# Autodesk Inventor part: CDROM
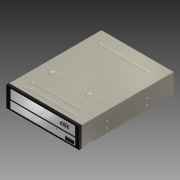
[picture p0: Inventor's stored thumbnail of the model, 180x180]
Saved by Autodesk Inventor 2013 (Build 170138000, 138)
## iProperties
Company: Autodesk Inc.
Created: 2005-12
Part Number: CDROM
Document SubType Name: Modeling
Designer: Autodesk Inc.
Density: 1 g/cm^3
Mass: 1074.93 g
Surface Area: 916.609 cm^2
Volume: 1074.93 cm^3
Material: Allgemein
Title: Personal Computer
Author: Autodesk Inc.
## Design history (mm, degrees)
sketch "Sketch5"
  geometry: L1 (0, 0)-(40, 0); L2 (40, 0)-(40, 145); L3 (40, 145)-(0, 145); L4 (0, 145)-(0, 0)
  constraints: 8 end point, 2 parallel, 1 horizontal, 1 perpendicular
  dimensions: "d189" = 145 distance of L3.end L1.start; "d190" = 40 distance of L1.start L1.end
extrude "Extrusion1" new body sketch "Sketch5" distance "d1" = 190; taper "d2" = 0 deg
sketch "Sketch6"
  geometry: L1 (-190, 72.5)-(0, 72.5); L2 (-168, 122.5)-(-162, 122.5); L3 (-162, 122.5)-(-162, 22.5); L4 (-162, 22.5)-(-168, 22.5); L5 (-168, 22.5)-(-168, 122.5); L6 (-18, 122.5)-(-12, 122.5); L7 (-12, 122.5)-(-12, 22.5); L8 (-12, 22.5)-(-18, 22.5); L9 (-18, 22.5)-(-18, 122.5); L10 (-33, 122.5)-(-27, 122.5); L11 (-27, 122.5)-(-27, 22.5); L12 (-27, 22.5)-(-33, 22.5); L13 (-33, 22.5)-(-33, 122.5); L14 (-72, 120)-(-60, 120); L15 (-60, 120)-(-60, 100); L16 (-60, 100)-(-72, 100); L17 (-72, 100)-(-72, 120); L18 (-72, 45)-(-72, 25); L19 (-60, 45)-(-72, 45); L20 (-72, 25)-(-60, 25); L21 (-60, 25)-(-60, 45); L22 (-190, 145)-(-190, 0) reference; L23 (0, 0)-(-190, 0) reference; L24 (0, 145)-(0, 0) reference; L25 (0, 145)-(-190, 145) reference; 10 further points
  constraints: 42 end point, 10 horizontal alignment, 10 parallel, 8 midpoint, 8 symmetric about line, 6 horizontal, 4 perpendicular, 21 other
  dimensions: "d4" = 6 distance between parallel lines of L5 L3; "d5" = 100 distance of L2.end L3.end; "d10" = 9 distance between parallel lines of L9 L11; "d12" = 12 distance of L14.start L14.end; "d13" = 20 distance of L16.end L14.start
extrude "Extrusion2" cut sketch "Sketch6" distance "d6" = 2; taper "d7" = 0 deg
feature "FaceDraft6" dims angle "d217" = 50 deg
sketch "Sketch8"
  geometry: L1 (-35, 142)-(-19, 142); L2 (-19, 142)-(-19, 3); L3 (-19, 3)-(-35, 3); L4 (-35, 3)-(-35, 142); L5 (-40, 0)-(-40, 145); L6 (0, 0)-(-40, 0); L7 (-40, 0)-(-40, 145) reference; L8 (0, 0)-(-40, 0) reference; L9 (0, 145)-(0, 0) reference; L10 (-40, 145)-(0, 145) reference
  constraints: 12 end point, 2 parallel, 1 horizontal, 1 perpendicular
  dimensions: "d20" = 16 distance of L1.start L1.end; "d191" = 139 distance of L1.end L2.end; "d192" = 5 distance between parallel lines of L5 L4; "d193" = 3 distance between parallel lines of L6 L3
extrude "Extrusion3" cut sketch "Sketch8" distance "d21" = 12; taper "d22" = 0 deg
workplane "Work Plane1"
sketch "Sketch9"
  geometry: L1 (-35, 8.726)-(-27.5, 8.726); L2 (-27.5, 8.726)-(-27.5, 31.566); L3 (-27.5, 31.566)-(-35, 31.566); L4 (-35, 31.566)-(-35, 8.726); L5 (-34.5, 31.066)-(-29.63, 31.066); L6 (-28, 29.436)-(-28, 11.356); L7 (-29.63, 9.726)-(-34.5, 9.726); L8 (-34.5, 9.726)-(-34.5, 31.066); L9 (-35, 31.566)-(-27.5, 31.566); L10 (-27.5, 31.566)-(-27.5, 88.946); L11 (-27.5, 88.946)-(-35, 88.946); L12 (-35, 88.946)-(-35, 31.566); L13 (-34.4, 87.946)-(-28, 87.946); L14 (-28, 87.946)-(-28, 32.066); L15 (-28, 32.066)-(-34.4, 32.066); L16 (-34.4, 32.066)-(-34.4, 87.946); L17 (-35, 108.946)-(-27.5, 108.946); L18 (-27.5, 108.946)-(-27.5, 107.946); L19 (-27.5, 107.946)-(-35, 107.946); L20 (-35, 107.946)-(-35, 108.946); L21 (-35, 127.946)-(-27.5, 127.946); L22 (-27.5, 127.946)-(-27.5, 126.946); L23 (-27.5, 126.946)-(-35, 126.946); L24 (-35, 126.946)-(-35, 127.946); L25 (-30, 108.946)-(-30, 111.946); L26 (-30, 111.946)-(-29, 111.946); L27 (-29, 111.946)-(-29, 117.946); L28 (-29, 117.946)-(-30, 117.946); L29 (-30, 117.946)-(-30, 120.946); L30 (-35, 126.946)-(-34, 126.946); L31 (-34, 126.946)-(-34, 108.946); L32 (-34, 108.946)-(-35, 108.946); L33 (-35, 108.946)-(-35, 126.946); L34 (-34, 120.946)-(-29.5, 120.946); L35 (-29.5, 120.946)-(-29.5, 121.946); L36 (-29.5, 121.946)-(-34, 121.946); L37 (-34, 121.946)-(-34, 120.946); L38 (-29.5, 120.946)-(-29.5, 118.446); L39 (-29.5, 118.446)-(-28.5, 118.446); L40 (-28.5, 118.446)-(-28.5, 111.446); L41 (-28.5, 111.446)-(-29.5, 111.446); L42 (-29.5, 111.446)-(-29.5, 108.946); L43 (-29.5, 120.946)-(-30, 120.946); L44 (-30, 121.946)-(-28.5, 121.946); L45 (-28.5, 121.946)-(-28.5, 122.446); L46 (-28.5, 122.446)-(-30, 122.446); L47 (-30, 122.446)-(-30, 121.946); L48 (-28.5, 122.446)-(-29, 122.446); L49 (-29, 122.446)-(-29, 126.446); L50 (-29, 126.446)-(-28.5, 126.446); L51 (-28.5, 126.446)-(-28.5, 122.446); L52 (-28.5, 126.446)-(-30, 126.446); L53 (-30, 126.446)-(-30, 126.946); L54 (-30, 126.946)-(-28.5, 126.946); L55 (-28.5, 126.946)-(-28.5, 126.446); L56 (-29.5, 120.946)-(-30, 120.946); L57 (-29.5, 108.946)-(-30, 108.946); L58 (-35, 142)-(-19, 142) reference; L59 (-35, 3)-(-35, 142) reference; L60 (-28, 29.436)-(-29.63, 31.066); L61 (-28, 11.356)-(-29.63, 9.726)
  constraints: 118 end point, 27 parallel, 15 collinear, 14 perpendicular, 11 horizontal, 6 equal length, 5 point on line, 2 vertical alignment, 4 other
  dimensions: "d25" = 1 distance between parallel lines of L1 L7; "d26" = 0.5 distance between parallel lines of L2 L6; "d28" = 0.5 distance between parallel lines of L5 L3; "d29" = 21.34 distance between parallel lines of L7 L5; "d31" = 1 distance between parallel lines of L5 L15; "d32" = 55.88 distance between parallel lines of L15 L13; "d33" = 1 distance between parallel lines of L13 L11; "d34" = 1 distance of L17.end L18.end; "d35" = 19 distance between parallel lines of L19 L11; "d36" = 18 distance between parallel lines of L17 L23; "d37" = 3 distance of L25.start L25.end; "d38" = 1 distance of L25.end L26.end; "d39" = 4 distance between parallel lines of L31 L25; "d40" = 6 distance of L26.end L27.end; "d41" = 0.5 distance between parallel lines of L27 L40; "d42" = 0.5 distance between parallel lines of L23 L52; "d195" = 6.4 distance of L14.end L15.end; "d196" = 0.5 distance between parallel lines of L4 L8 (derived); "d197" = 2.305 distance of L6.start L5.end; "d198" = 135 deg angle of L60 L6; "d199" = 2.305 distance of L6.end L7.start; "d200" = 135 deg angle of L7 L61
extrude "Extrusion4" join sketch "Sketch9" stored distance "d43" = 10; taper "d44" = 0 deg
sketch "Sketch11"
  geometry: L1 (-28, 87.946)-(-28, 32.066) reference; L2 (-28, 32.066)-(-34.4, 32.066) reference; L3 (-28, 62.566)-(-27.5, 62.566); L4 (-27.5, 62.566)-(-27.5, 57.066); L5 (-27.5, 57.066)-(-28, 57.066); L6 (-28, 57.066)-(-28, 62.566)
  constraints: 8 end point, 2 parallel, 1 horizontal, 1 perpendicular, 1 point on line
  dimensions: "d49" = 25 distance between parallel lines of L2 L5; "d50" = 5.5 distance between parallel lines of L5 L3
extrude "Extrusion6" cut sketch "Sketch11" stored distance "d51" = 2; taper "d52" = 0 deg
sketch "Sketch13"
  geometry: L1 (-31.25, 31.03)-(-31.25, 9.03); L2 (-34.5, 9.726)-(-34.5, 31.066); L3 (-34.5, 31.066)-(-29.63, 31.066); L4 (-28, 29.436)-(-28, 11.356); L5 (-28, 20.396)-(-34.5, 20.396); C1 r 1.25 at (-31.25, 22.53); C2 r 1.25 at (-31.25, 26.798); C3 r 1.25 at (-31.25, 18.262); C4 r 1.25 at (-31.25, 13.994)
  constraints: 10 end point, 4 centre point, 4 point on line, 3 equal radius, 2 midpoint, 1 perpendicular
  dimensions: "d60" = 4.268 distance of C3.centre C1.centre; "d61" = 4.268 distance of C1.centre C2.centre (= d60); "d62" = 2.5 diameter of C2; "d204" = 4.268 distance of C4.centre C3.centre (derived); "d205" = 2.134 distance from line of L5 C1.centre (derived)
extrude "Extrusion8" join sketch "Sketch13" distance "d63" = 3; taper "d64" = 0 deg
sketch "Sketch14"
  geometry: C1 r 0.9 at (0, 0); C2 r 0.9 at (0, -4.268); C3 r 0.9 at (0, -8.536); C4 r 0.9 at (0, -12.804); C5 r 1.25 at (0, -4.268) reference; C6 r 1.25 at (0, -12.804) reference; C7 r 1.25 at (0, -8.536) reference
  constraints: 4 centre point, 3 equal radius
  dimensions: "d65" = 1.8 diameter of C1
extrude "Extrusion9" join sketch "Sketch14" distance "d66" = 5; taper "d67" = 0 deg
sketch "Sketch15"
  geometry: L1 (-34.5, 88)-(-34.5, 31); L2 (-25.5, 88)-(-34.5, 88); L3 (-27.5, 107.946)-(-35, 107.946) reference; L4 (-35, 107.946)-(-35, 88.946) reference; L5 (-35, 88.946)-(-27.5, 88.946) reference; L6 (-27.5, 88.946)-(-27.5, 62.566) reference; L7 (-27.5, 62.566)-(-28, 62.566) reference; L8 (-28, 62.566)-(-28, 87.946) reference; L9 (-28, 87.946)-(-34.4, 87.946) reference; L10 (-34.4, 87.946)-(-34.4, 32.066) reference; L11 (-34.4, 32.066)-(-28, 32.066) reference; L12 (-28, 32.066)-(-28, 57.066) reference; L13 (-28, 57.066)-(-27.5, 57.066) reference; L14 (-27.5, 57.066)-(-27.5, 8.726) reference; L15 (-27.5, 8.726)-(-35, 8.726) reference; L16 (-35, 8.726)-(-35, 3) reference; L17 (-35, 3)-(-19, 3) reference; L18 (-19, 3)-(-19, 142) reference; L19 (-19, 142)-(-35, 142) reference; L20 (-35, 142)-(-35, 127.946) reference; L21 (-35, 127.946)-(-27.5, 127.946) reference; L22 (-27.5, 127.946)-(-27.5, 126.946) reference; L23 (-27.5, 126.946)-(-28.5, 126.946) reference; L24 (-28.5, 126.946)-(-28.5, 121.946) reference; L25 (-28.5, 121.946)-(-29.5, 121.946) reference; L26 (-29.5, 121.946)-(-29.5, 118.446) reference; L27 (-29.5, 118.446)-(-28.5, 118.446) reference; L28 (-28.5, 118.446)-(-28.5, 111.446) reference; L29 (-28.5, 111.446)-(-29.5, 111.446) reference; L30 (-29.5, 111.446)-(-29.5, 108.946) reference; L31 (-29.5, 108.946)-(-27.5, 108.946) reference; L32 (-27.5, 108.946)-(-27.5, 107.946) reference; C1 r 0.5 at (-32.5, 84)
  constraints: 4 end point, 1 centre point
  dimensions: "d69" = 4 distance from line of C1.centre L2; "d70" = 1 diameter of C1; "d71" = 2 distance from line of L1 C1.centre
extrude "Extrusion10" join sketch "Sketch15" distance "d72" = 10; taper "d73" = 0 deg
workplane "Work Plane3"
sketch "Sketch16"
  geometry: L1 (-30, 111.946)-(-30, 108.946) reference; L2 (-30, 126.946)-(-30, 126.446) reference; L3 (-30, 126.946)-(-27, 126.946); L4 (-27, 126.946)-(-27, 108.946); L5 (-27, 108.946)-(-30, 108.946); L6 (-30, 108.946)-(-30, 126.946)
  constraints: 8 end point, 2 parallel, 1 horizontal, 1 perpendicular
  dimensions: "d81" = 3 distance between parallel lines of L6 L4
extrude "Extrusion11" cut sketch "Sketch16" stored distance "d82" = 10; taper "d83" = 0 deg
sketch "Sketch17"
  geometry: L1 (-34, 120.946)-(-30, 120.946) reference; L2 (-30, 127)-(-29.8, 127); L3 (-29.8, 127)-(-29.8, 126.246); L4 (-29.8, 126.246)-(-30, 126.246); L5 (-30, 126.246)-(-30, 127); L6 (-30, 121.946)-(-34, 121.946) reference; L7 (-30, 121.946)-(-29.8, 121.946); L8 (-29.8, 121.946)-(-29.8, 122.7); L9 (-29.8, 122.7)-(-30, 122.7); L10 (-30, 122.7)-(-30, 121.946); L11 (-30, 117.946)-(-29, 117.946) reference; L12 (-29, 111.946)-(-30, 111.946) reference; L13 (-30, 120.946)-(-29.8, 120.946); L14 (-29.8, 120.946)-(-29.8, 116.946); L15 (-29.8, 116.946)-(-30, 116.946); L16 (-30, 116.946)-(-30, 120.946); L17 (-30, 109)-(-29.8, 109); L18 (-29.8, 109)-(-29.8, 112.946); L19 (-29.8, 112.946)-(-30, 112.946); L20 (-30, 112.946)-(-30, 109); L21 (-30, 126.446)-(-29, 126.446) reference
  constraints: 32 end point, 8 parallel, 4 horizontal, 4 perpendicular, 3 collinear
  dimensions: "d84" = 1 distance between parallel lines of L15 L11; "d85" = 1 distance between parallel lines of L19 L12 (= d84); "d87" = 0.2 distance between parallel lines of L4 L21 (= d86); "d88" = 0.2 distance between parallel lines of L5 L3
extrude "Extrusion12" join sketch "Sketch17" stored distance "d89" = 10; taper "d90" = 0 deg
sketch "Sketch18"
  geometry: L1 (-35, 108)-(-35, 89); L2 (-30, 127.04)-(-34, 127.04); L3 (-34, 122)-(-30, 122); L4 (-30, 121.108)-(-34, 121); L5 (-32, 127.04)-(-32, 122); L6 (-32, 121.054)-(-32, 108.946); L7 (-32, 124.52)-(-30.923, 124.52); L8 (-32, 115)-(-31.161, 115); L9 (-35, 107.946)-(-35, 88.946) reference; L10 (-29.8, 126.246)-(-30, 126.246) reference; L11 (-30.73, 98.446)-(-33.27, 98.446); L12 (-30, 108.946)-(-34, 108.946) reference; C1 r 0.25 at (-32, 125.79); C2 r 0.25 at (-32, 123.25); C3 r 0.25 at (-32, 118.81); C4 r 0.25 at (-32, 116.27); C5 r 0.25 at (-32, 113.73); C6 r 0.25 at (-32, 111.19); C7 r 0.25 at (-30.73, 102.446); C8 r 0.25 at (-30.73, 98.446); C9 r 0.25 at (-30.73, 94.446); C10 r 0.25 at (-33.27, 102.446); C11 r 0.25 at (-33.27, 98.446); C12 r 0.25 at (-33.27, 94.446); 2 further points
  constraints: 18 end point, 12 centre point, 11 equal radius, 8 midpoint, 6 point on line, 5 vertical alignment, 4 horizontal alignment, 3 symmetric about line, 2 parallel, 1 perpendicular
  dimensions: "d91" = 2.54 distance of C2.centre C1.centre; "d92" = 2.54 distance of C5.centre C4.centre; "d93" = 2.54 distance of C4.centre C3.centre (= d92); "d94" = 0.5 diameter of C1; "d95" = 2.54 distance of C10.centre C7.centre; "d96" = 4 distance of L11.start C7.centre; "d97" = 4 distance of C9.centre L11.start (= d96)
extrude "Extrusion13" join sketch "Sketch18" distance "d101" = 8; taper "d102" = 0 deg
sketch "Sketch19"
  geometry: L1 (-25, 56)-(-25, 7); L2 (-19, 3)-(-19, 142); L3 (-19, 31)-(-24.8, 31); L4 (-24.8, 31)-(-24.8, 30.2); L5 (-24.8, 30.2)-(-19, 30.2); L6 (-19, 30.2)-(-19, 31); L7 (-19, 89)-(-24.8, 89); L8 (-24.8, 89)-(-24.8, 88.2); L9 (-24.8, 88.2)-(-19, 88.2); L10 (-19, 88.2)-(-19, 89); L11 (-19, 128)-(-24.8, 128); L12 (-24.8, 128)-(-24.8, 127.2); L13 (-24.8, 127.2)-(-19, 127.2); L14 (-19, 127.2)-(-19, 128)
  constraints: 28 end point, 6 parallel, 4 collinear, 3 horizontal, 3 perpendicular, 3 point on line
  dimensions: "d103" = 0.2 distance between parallel lines of L1 L4; "d104" = 0.8 distance between parallel lines of L5 L3
extrude "Extrusion14" join sketch "Sketch19" distance "d105" = 11; taper "d106" = 0 deg
sketch "Sketch20"
  geometry: L1 (166, 145)-(181, 145); L2 (181, 145)-(181, 139); L3 (181, 139)-(166, 139); L4 (166, 139)-(166, 145); L5 (15, 145)-(30, 145); L6 (30, 145)-(30, 139); L7 (30, 139)-(15, 139); L8 (15, 139)-(15, 145); L9 (15, 0)-(30, 0); L10 (30, 0)-(30, 6); L11 (30, 6)-(15, 6); L12 (15, 6)-(15, 0); L13 (166, 0)-(181, 0); L14 (181, 0)-(181, 6); L15 (181, 6)-(166, 6); L16 (166, 6)-(166, 0); 4 further points
  constraints: 32 end point, 8 parallel, 6 collinear, 4 horizontal, 4 horizontal alignment, 4 midpoint, 4 perpendicular, 2 equal length, 8 other
  dimensions: "d110" = 15 distance of L1.start L1.end; "d111" = 6 distance of L3.end L1.start
extrude "Extrusion15" cut sketch "Sketch20" distance "d114" = 3; taper "d115" = 0 deg
feature "FaceDraft5" dims angle "d216" = 40 deg
sketch "Sketch21"
  geometry: L1 (30, 0)-(30, 6); L2 (15, 6)-(15, 0); L3 (15, 145)-(15, 139); L4 (30, 139)-(30, 145); L5 (166, 145)-(166, 139); L6 (181, 139)-(181, 145); L7 (166, 145)-(181, 145); L8 (15, 145)-(30, 145); L9 (30, 0)-(15, 0); C1 r 3 at (22.5, 139); C2 r 3 at (173.5, 139); C3 r 3 at (173.5, 6); C4 r 3 at (22.5, 6); A1 r 7.5 centre (22.5, 6) between (30, 6) and (15, 6); A2 r 7.5 centre (22.5, 139) between (15, 139) and (30, 139); A3 r 7.5 centre (173.5, 139) between (166, 139) and (181, 139)
  constraints: 18 end point, 7 centre point, 6 point on circle, 3 coincident, 3 equal radius
  dimensions: "d117" = 6 diameter of C1
extrude "Extrusion16" join sketch "Sketch21" distance "d118" = 2; taper "d119" = 0 deg
fillet "Fillet9" dims "d210" = 1
sketch "Sketch22"
  geometry: L1 (-0.25, 1.75)-(0.25, 1.75); L2 (0.25, 1.75)-(0.25, -1.75); L3 (0.25, -1.75)-(-0.25, -1.75); L4 (-0.25, -1.75)-(-0.25, 1.75); L5 (-1.75, 0.25)-(1.75, 0.25); L6 (1.75, 0.25)-(1.75, -0.25); L7 (1.75, -0.25)-(-1.75, -0.25); L8 (-1.75, -0.25)-(-1.75, 0.25); L9 (0, 0)-(0, 1.021); L10 (0, 0)-(1.024, 0); L11 (151, 0)-(151, 3); L12 (151, 0)-(154, 0); L13 (150.75, 1.75)-(151.25, 1.75); L14 (151.25, 1.75)-(151.25, -1.75); L15 (151.25, -1.75)-(150.75, -1.75); L16 (150.75, -1.75)-(150.75, 1.75); L17 (149.25, 0.25)-(152.75, 0.25); L18 (152.75, 0.25)-(152.75, -0.25); L19 (152.75, -0.25)-(149.25, -0.25); L20 (149.25, -0.25)-(149.25, 0.25); L21 (0, -133)-(0, -130); L22 (0, -133)-(3, -133); L23 (151, -133)-(151, -130); L24 (151, -133)-(154, -133); L25 (150.75, -131.25)-(151.25, -131.25); L26 (151.25, -131.25)-(151.25, -134.75); L27 (151.25, -134.75)-(150.75, -134.75); L28 (150.75, -134.75)-(150.75, -131.25); L29 (149.25, -132.75)-(152.75, -132.75); L30 (152.75, -132.75)-(152.75, -133.25); L31 (152.75, -133.25)-(149.25, -133.25); L32 (149.25, -133.25)-(149.25, -132.75); L33 (-0.25, -131.25)-(0.25, -131.25); L34 (0.25, -131.25)-(0.25, -134.75); L35 (0.25, -134.75)-(-0.25, -134.75); L36 (-0.25, -134.75)-(-0.25, -131.25); L37 (-1.75, -132.75)-(1.75, -132.75); L38 (1.75, -132.75)-(1.75, -133.25); L39 (1.75, -133.25)-(-1.75, -133.25); L40 (-1.75, -133.25)-(-1.75, -132.75); C1 r 3 at (0, 0); C2 r 3 at (0, 0) reference; A1 r 3 centre (151, 0) between (151, 3) and (154, 0); A2 r 3 centre (0, -133) between (0, -130) and (3, -133); A3 r 3 centre (151, -133) between (151, -130) and (154, -133)
  constraints: 80 end point, 18 parallel, 14 equal length, 14 perpendicular, 8 horizontal, 6 point on circle, 4 centre point, 16 other
  dimensions: "d120" = 0.5 distance of L1.start L1.end; "d121" = 3.5 distance of L3.end L1.start
extrude "Extrusion17" cut sketch "Sketch22" distance "d122" = 1; taper "d123" = 0 deg
sketch "Sketch23"
  geometry: L1 (-190, 0)-(-190, 40); L2 (-30, 40)-(-166, 40); C1 r 1.4 at (-137, 30.5); C2 r 1.4 at (-137, 18.5); C3 r 1.571 at (-57, 30.5); C4 r 1.571 at (-57, 18.5)
  constraints: 4 centre point, 4 end point, 2 equal radius, 2 horizontal alignment, 2 vertical alignment
  dimensions: "d125" = 53 distance from line of L1 C1.centre; "d126" = 80 distance of C3.centre C1.centre; "d127" = 2.8 diameter of C1; "d128" = 9.5 distance from line of C1.centre L2; "d129" = 12 distance of C2.centre C1.centre
extrude "Extrusion18" cut sketch "Sketch23" distance "d130" = 5; taper "d131" = 0 deg
sketch "Sketch24"
  geometry: L1 (40, 145)-(0, 145); L2 (0, 145)-(0, 0); L3 (0, 0)-(40, 0); L4 (40, 0)-(40, 145); L5 (-0.5, 145.5)-(40.5, 145.5); L6 (40.5, 145.5)-(40.5, -0.5); L7 (40.5, -0.5)-(-0.5, -0.5); L8 (-0.5, -0.5)-(-0.5, 145.5); L9 (0, 0)-(40, 0) reference; L10 (40, 0)-(40, 145) reference; L11 (40, 145)-(0, 145) reference; L12 (0, 145)-(0, 0) reference
  constraints: 16 end point, 3 other
  dimensions: "d132" = 0.5 distance between parallel lines of L1 L5
extrude "Extrusion19" join sketch "Sketch24" distance "d133" = 5; taper "d134" = 0 deg
sketch "Sketch25"
  geometry: L1 (-0.5, 145.5)-(40.5, 145.5); L2 (-0.5, -0.5)-(-0.5, 145.5); L3 (40.5, -0.5)-(-0.5, -0.5); L4 (40.5, 145.5)-(40.5, -0.5); L5 (1.5, 138.5)-(38.5, 138.5); L6 (38.5, 138.5)-(38.5, 6.5); L7 (38.5, 6.5)-(1.5, 6.5); L8 (1.5, 6.5)-(1.5, 138.5); L9 (-0.5, 145.5)-(40.5, 145.5) reference; L10 (-0.5, -0.5)-(-0.5, 145.5) reference; L11 (40.5, -0.5)-(-0.5, -0.5) reference; L12 (40.5, 145.5)-(40.5, -0.5) reference
  constraints: 16 end point, 2 parallel, 1 horizontal, 1 perpendicular
  dimensions: "d135" = 7 distance between parallel lines of L5 L1; "d136" = 7 distance between parallel lines of L3 L7 (= d135); "d137" = 2 distance between parallel lines of L2 L8; "d138" = 2 distance between parallel lines of L4 L6 (= d137)
extrude "Extrusion20" cut sketch "Sketch25" distance "d139" = 0.5; taper "d140" = 0 deg
sketch "Sketch26"
  geometry: L1 (1.5, 138.5)-(1.5, 6.5); L2 (1.5, 6.5)-(38.5, 6.5); L3 (38.5, 138.5)-(1.5, 138.5); L4 (3, 137)-(21, 137); L5 (21, 137)-(21, 8); L6 (21, 8)-(3, 8); L7 (3, 8)-(3, 137); L8 (1.5, 138.5)-(1.5, 6.5) reference; L9 (1.5, 6.5)-(38.5, 6.5) reference; L10 (38.5, 6.5)-(38.5, 138.5) reference; L11 (38.5, 138.5)-(1.5, 138.5) reference
  constraints: 14 end point, 2 parallel, 1 horizontal, 1 perpendicular
  dimensions: "d141" = 1.5 distance between parallel lines of L1 L7; "d142" = 1.5 distance between parallel lines of L4 L3 (= d141); "d143" = 18 distance of L4.start L4.end; "d144" = 1.5 distance between parallel lines of L2 L6 (= d142)
extrude "Extrusion21" join sketch "Sketch26" distance "d145" = 0.6; taper "d146" = 0 deg
sketch "Sketch27"
  geometry: L1 (21, 137)-(21, 8); L2 (1.5, 6.5)-(38.5, 6.5); L3 (38.5, 6.5)-(38.5, 138.5); L4 (38.5, 138.5)-(1.5, 138.5); L5 (22.5, 138.5)-(22.5, 6.5); L6 (21, 137)-(21, 8) reference; L7 (21, 8)-(3, 8) reference; L8 (3, 8)-(3, 137) reference; L9 (3, 137)-(21, 137) reference; L10 (1.5, 138.5)-(1.5, 6.5) reference; L11 (1.5, 6.5)-(38.5, 6.5) reference; L12 (38.5, 6.5)-(38.5, 138.5) reference; L13 (38.5, 138.5)-(1.5, 138.5) reference
  constraints: 10 end point, 2 point on line, 1 perpendicular
  dimensions: "d147" = 1.5 distance between parallel lines of L1 L5
extrude "Extrusion22" join sketch "Sketch27" distance "d148" = 0.3; taper "d149" = 0 deg
sketch "Sketch28"
  geometry: L1 (38.5, 6.5)-(22.5, 6.5); L2 (38.5, 138.5)-(38.5, 6.5); L3 (22.5, 138.5)-(38.5, 138.5); L4 (22.5, 6.5)-(22.5, 138.5); L5 (37.5, 137.5)-(37.5, 7.5); L6 (37.5, 7.5)-(23.5, 7.5); L7 (23.5, 7.5)-(23.5, 137.5); L8 (23.5, 137.5)-(37.5, 137.5); L9 (38.5, 6.5)-(22.5, 6.5) reference; L10 (38.5, 138.5)-(38.5, 6.5) reference; L11 (22.5, 138.5)-(38.5, 138.5) reference; L12 (22.5, 6.5)-(22.5, 138.5) reference
  constraints: 16 end point, 3 other
  dimensions: "d150" = 1 distance between parallel lines of L3 L8
extrude "Extrusion23" join sketch "Sketch28" distance "d151" = 0.2; taper "d152" = 0 deg
sketch "Sketch29"
  geometry: L1 (37.5, 137.5)-(37.5, 7.5); L2 (23.5, 137.5)-(37.5, 137.5); L3 (29.5, 117)-(36.5, 117); L4 (36.5, 117)-(36.5, 135.5); L5 (36.5, 135.5)-(29.5, 135.5); L6 (29.5, 135.5)-(29.5, 117); L7 (37.5, 7.5)-(23.5, 7.5) reference; L8 (37.5, 137.5)-(37.5, 7.5) reference; L9 (23.5, 137.5)-(37.5, 137.5) reference; L10 (23.5, 7.5)-(23.5, 137.5) reference
  constraints: 12 end point, 2 parallel, 1 horizontal, 1 perpendicular
  dimensions: "d153" = 7 distance of L3.start L3.end; "d154" = 18.5 distance of L5.end L3.start; "d155" = 2 distance between parallel lines of L2 L5; "d156" = 1 distance between parallel lines of L1 L4
extrude "Extrusion24" cut sketch "Sketch29" distance "d157" = 5; taper "d158" = 0 deg
sketch "Sketch30"
  geometry: L1 (36.5, 117)-(36.5, 135.5); L2 (36.5, 135.5)-(29.5, 135.5); L3 (29.5, 135.5)-(29.5, 117); L4 (29.5, 117)-(36.5, 117); L5 (30, 135)-(36, 135); L6 (36, 135)-(36, 117.5); L7 (36, 117.5)-(30, 117.5); L8 (30, 117.5)-(30, 135); L9 (36.5, 117)-(36.5, 135.5) reference; L10 (36.5, 135.5)-(29.5, 135.5) reference; L11 (29.5, 135.5)-(29.5, 117) reference; L12 (29.5, 117)-(36.5, 117) reference
  constraints: 16 end point, 3 other
  dimensions: "d159" = 0.5 distance between parallel lines of L2 L5
extrude "Extrusion25" join sketch "Sketch30" distance "d160" = 4; taper "d161" = 0 deg
workplane "Work Plane5"
loft "Loft1" dims "d168" = 0, "d169" = 90 deg, "d170" = 0, "d171" = 90 deg
  node "Edges1"
sketch "Sketch32"
  geometry: L1 (23.5, 7.5)-(23.5, 137.5); L2 (-0.5, 145.5)-(40.5, 145.5); L3 (36.5, 135.5)-(36.5, 117) reference; L4 (36.5, 117)-(29.5, 117) reference; L5 (29.5, 117)-(29.5, 135.5) reference; L6 (29.5, 135.5)-(36.5, 135.5) reference; L7 (37.5, 7.5)-(23.5, 7.5) reference; L8 (37.5, 137.5)-(37.5, 7.5) reference; L9 (23.5, 137.5)-(37.5, 137.5) reference; L10 (23.5, 7.5)-(23.5, 137.5) reference; C1 r 0.75 at (25.5, 100.5)
  constraints: 4 end point, 1 centre point
  dimensions: "d177" = 2 distance from line of C1.centre L1; "d178" = 45 distance from line of L2 C1.centre; "d179" = 1.5 diameter of C1
extrude "Extrusion26" cut sketch "Sketch32" distance "d180" = 5; taper "d181" = 0 deg
sketch "Sketch33"
  geometry: L1 (112.441, -6.979)-(126.65, -6.979); L2 (126.65, -6.979)-(126.65, -9.367); L3 (126.65, -9.367)-(112.441, -9.367); L4 (112.441, -9.367)-(112.441, -6.979); L5 (106.529, -7.703)-(123.298, -7.703); L6 (123.298, -7.703)-(123.298, -13.799); L7 (123.298, -13.799)-(106.529, -13.799); L8 (106.529, -13.799)-(106.529, -7.703)
  constraints: 4 other
extrude "Extrusion27" join sketch "Sketch33" distance "d182" = 0.1; taper "d183" = 0 deg
sketch "Sketch34"
  geometry: L1 (7.703, 113.208)-(7.703, 114.553) reference; L2 (8.946, 113.208)-(7.703, 113.208) reference; L3 (8.946, 114.553)-(8.946, 113.208) reference; L4 (7.703, 114.553)-(8.946, 114.553) reference
extrude "Extrusion28" cut sketch "Sketch34" distance "d184" = 0.1; taper "d185" = 0 deg
extrude "Extrusion29" join sketch "Sketch33" distance "d186" = 0.1; taper "d187" = 0 deg
fillet "Fillet10" dims "d211" = 1, "d212" = 1
fillet "Fillet11" dims "d213" = 2
sketch "Sketch35"
  geometry: C1 r 1.571 at (133, 21.5) reference; C2 r 1.571 at (133, 9.5) reference; C3 r 1.4 at (53, 21.5) reference; C4 r 1.4 at (53, 9.5) reference
extrude "Extrusion30" cut sketch "Sketch35" distance "d214" = 5; taper "d215" = 0 deg
sketch "Sketch36"
  geometry: L1 (-28, 62.566)-(-28, 87.946) reference; L2 (-28, 87.946)-(-34.4, 87.946) reference; L3 (-28, 32.066)-(-28, 57.066) reference; L4 (-28, 57.066)-(-27.5, 57.066) reference; L5 (-28, 32.066)-(-34.4, 32.066); L6 (-34.4, 32.066)-(-34.4, 87.946); L7 (-34.4, 87.946)-(-28, 87.946); L8 (-28, 87.946)-(-28, 32.066); L9 (-28, 62.566)-(-27.5, 62.566); L10 (-27.5, 62.566)-(-27.5, 57.066); L11 (-27.5, 57.066)-(-28, 57.066); L12 (-28, 57.066)-(-28, 62.566)
  constraints: 16 end point, 4 parallel, 2 horizontal, 2 perpendicular
extrude "Extrusion31" join sketch "Sketch36" distance "d225" = 5; taper "d226" = 0 deg
body "Solid1"
pattern_linear "Rectangular Pattern2" dims "d220" = 2.54, "d223" = 2.54
sketch "Sketch31"
  geometry: L1 (36, 135)-(36, 117.5) reference; L2 (30, 135)-(36, 135) reference; L3 (30, 117.5)-(30, 135) reference; L4 (36, 117.5)-(30, 117.5) reference; L5 (31.5, 132.5)-(34.5, 132.5); L6 (34.5, 132.5)-(34.5, 120); L7 (34.5, 120)-(31.5, 120); L8 (31.5, 120)-(31.5, 132.5); L9 (31.5, 132.5)-(31.5, 120); L10 (34.5, 132.5)-(34.5, 120); A1 r 3 centre (33, 135.098) between (31.5, 132.5) and (34.5, 132.5); A2 r 3 centre (33, 117.402) between (34.5, 120) and (31.5, 120)
  constraints: 12 end point, 4 point on circle, 3 equal length, 2 centre point, 1 equal radius, 1 horizontal, 1 perpendicular
  dimensions: "d163" = 2.5 distance between parallel lines of L5 L2; "d164" = 2.5 distance between parallel lines of L4 L7 (= d163); "d165" = 1.5 distance between parallel lines of L3 L8; "d166" = 1.5 distance between parallel lines of L1 L6 (= d165); "d167" = 3 radius of A1
node "Projected Loop10"
node "Projected Loop11"
node "Projected Loop12"
other parameters: "d86" = 0.2, "d16_1" = 142 [user parameter], "d201" = -0.5, "d206" = -5, "d224" = 0.5
